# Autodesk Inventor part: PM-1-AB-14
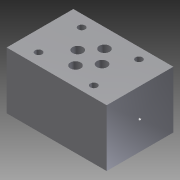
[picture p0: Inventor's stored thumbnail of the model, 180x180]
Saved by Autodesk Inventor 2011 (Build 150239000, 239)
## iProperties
Created: 2010-07
Part Number: PM-1-AB-14
Document SubType Name: Modeling
Designer: demin
Density: 1 g/cm^3
Author: demin
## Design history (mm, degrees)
sketch "Эскиз1"
  geometry: L1 (-36, 24)-(36, 24); L2 (36, 24)-(36, -24); L3 (36, -24)-(-36, -24); L4 (-36, -24)-(-36, 24); 3 further points
  constraints: 8 end point, 2 midpoint, 2 parallel, 1 horizontal, 1 horizontal alignment, 1 perpendicular, 1 vertical alignment
  dimensions: "d0" = 72 distance of L2.end L3.end; "d1" = 48 distance of L1.end L2.end
extrude "Выдавливание1" new body sketch "Эскиз1" distance "d2" = 41; taper "d3" = 0 deg
sketch "Эскиз2"
  geometry: L1 (36, 24)-(-36, 24) reference; L2 (-36, 24)-(-36, -24) reference; L3 (-36, -24)-(36, -24) reference; L4 (36, -24)-(36, 24) reference; L5 (0, -27.677)-(0, 30.39); L6 (43.053, 0)-(-43.957, 0); L7 (21.5, -19.443)-(21.5, -9.468); L8 (27.618, -15.5)-(16.626, -15.5); L9 (-15.221, -16.25)-(-22.32, -16.25); L10 (-19, -18.787)-(-19, -11.951); L11 (8.507, -10.4)-(-7.674, -10.4); L12 (8.8, -4.932)-(8.8, 4.52); L13 (-8.7, -4.932)-(-8.7, 4.52); L14 (4.866, 10.4)-(-8.152, 10.4); 9 further points
  constraints: 20 end point, 14 point on line, 7 perpendicular, 5 parallel, 2 midpoint
  dimensions: "d4" = 21.5 horizontal distance of L7.start L5.start; "d5" = 15.5 vertical distance of L6.start L8.start; "d6" = 0.75 vertical distance of L9.end L8.end; "d7" = 19 distance from line of L10 L5.start; "d28" = 5.1 vertical distance of L11.start L8.end; "d36" = 12.7 horizontal distance of L12.start L7.end; "d44" = 30.2 horizontal distance of L13.start L7.end; "d52" = 25.9 vertical distance of L14.start L8.end
hole "Отверстие1" sketch "Эскиз2" diameter "d8" = 5; stored, may be unused: countersink angle "d12" = 90 deg, drill point angle "d14" = 118 deg; dims "d9" = 6, "d10" = 4, "d11" = 2, "d13" = 8
hole "Отверстие2" sketch "Эскиз2" diameter "d15" = 5; stored, may be unused: countersink angle "d19" = 90 deg, drill point angle "d21" = 118 deg; dims "d16" = 6, "d17" = 4, "d18" = 2, "d20" = 8
pattern_linear "Прямоуг.массив1" dims "d24" = 31
pattern_linear "Прямоуг.массив2" dims "d27" = 32.5
hole "Отверстие3" sketch "Эскиз2" diameter "d29" = 7.5; stored, may be unused: countersink angle "d33" = 90 deg, drill point angle "d35" = 118 deg; dims "d30" = 6, "d31" = 12, "d32" = 1, "d34" = 8
hole "Отверстие4" sketch "Эскиз2" diameter "d37" = 7.5; stored, may be unused: countersink angle "d41" = 90 deg, drill point angle "d43" = 118 deg; dims "d38" = 6, "d39" = 12, "d40" = 1, "d42" = 8
hole "Отверстие5" sketch "Эскиз2" diameter "d45" = 7.5; stored, may be unused: countersink angle "d49" = 90 deg, drill point angle "d51" = 118 deg; dims "d46" = 6, "d47" = 12, "d48" = 1, "d50" = 8
hole "Отверстие6" sketch "Эскиз2" diameter "d53" = 7.5; stored, may be unused: countersink angle "d57" = 90 deg, drill point angle "d59" = 118 deg; dims "d54" = 6, "d55" = 12, "d56" = 1, "d58" = 8
sketch "Эскиз7"
  geometry: L1 (0, 48)-(-41, 0); L2 (-41, 48)-(0, 0); 2 further points
  constraints: 4 end point, 1 midpoint
hole "Отверстие9" sketch "Эскиз7" at (-20.5, 24) diameter "d82" = 2; stored, may be unused: countersink angle "d86" = 90 deg, drill point angle "d88" = 118 deg; dims "d83" = 6, "d84" = 4, "d85" = 2, "d87" = 20
sketch "Эскиз8"
  geometry: L1 (0, 0)-(0, 48) reference; L2 (41, 48)-(0, 0); L3 (0, 0)-(0, 48); L4 (41, 0)-(0, 48); 2 further points
  constraints: 6 end point, 2 midpoint, 1 collinear
hole "Отверстие10" sketch "Эскиз8" at (20.5, 24) diameter "d89" = 2; stored, may be unused: countersink angle "d93" = 90 deg, drill point angle "d95" = 118 deg; dims "d90" = 6, "d91" = 4, "d92" = 2, "d94" = 20
node "Твердое тело1"
